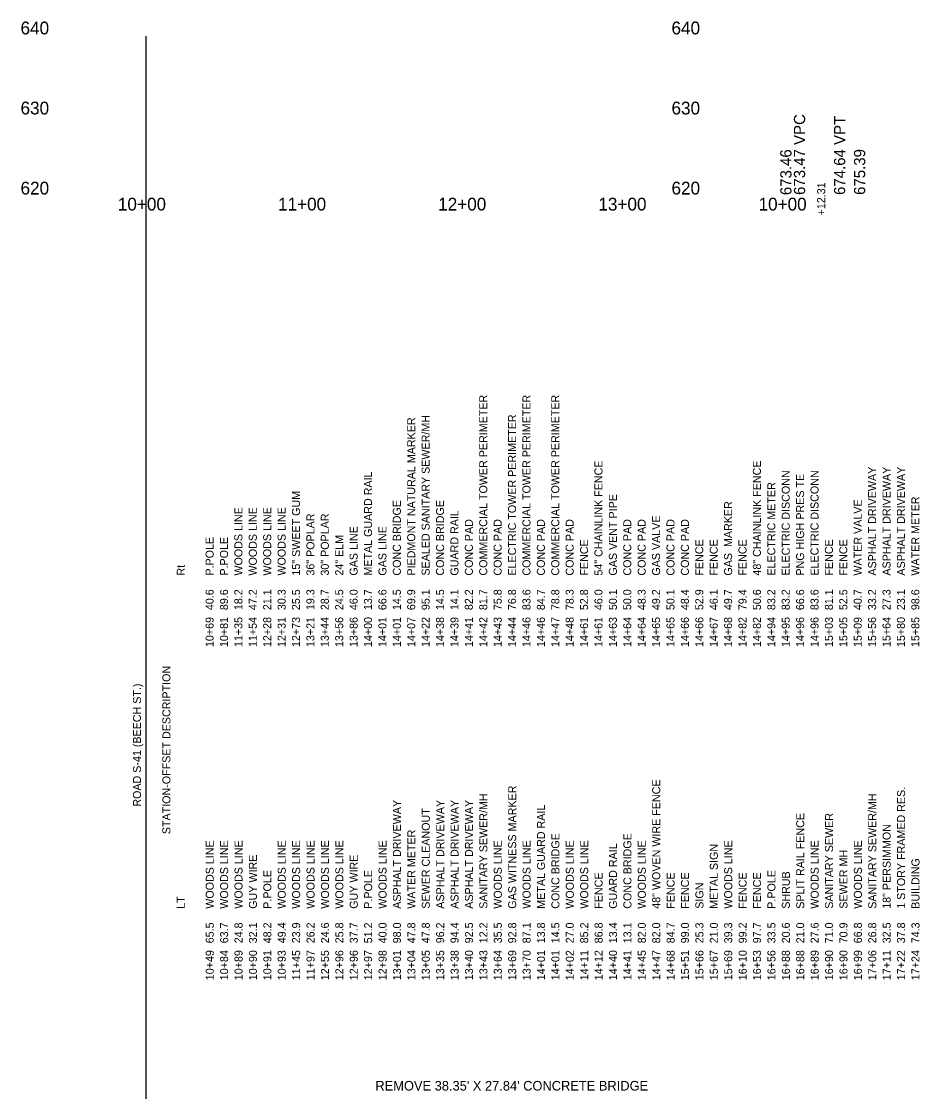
# Model space of a CAD drawing. Extents: x 16382402 to 16388022, y 46194326 to 46202918.
# Drawn here: x 16384274 to 16384834, y 46196212 to 46196880 of the extents above; entities that cross this region are included whole.
import ezdxf

# ---------------------------------------------------------------- set-up
doc = ezdxf.new("R2010")
doc.units = 0
for name, color, linetype in [('RD_DDB_ElevTX', 7, 'Continuous'), ('RD_DDB_Profile_Lbl', 7, 'Continuous'), ('RD_DDB_StaTX', 7, 'Continuous'), ('RD_DDB_StripGrade', 7, 'Continuous'), ('RD_EX_Bridge', 7, 'Continuous'), ('RD_GPK_Profile_Cell', 7, 'Continuous'), ('RD_TX_Bldg', 7, 'Continuous'), ('RD_TX_Misc1', 7, 'Continuous')]:
    doc.layers.add(name, color=color, linetype=linetype)

msp = doc.modelspace()

# ---------------------------------------------------------------- linework, layer by layer
at = {"layer": 'RD_GPK_Profile_Cell'}
msp.add_line((16384351.35, 46195620.8), (16384351.35, 46196870.8), dxfattribs=at)

# ---------------------------------------------------------------- texts
at = {"layer": 'RD_DDB_ElevTX'}
for s, p in [('640', (16384273.02, 46196871.8)), ('640', (16384679.41, 46196871.8)), ('630', (16384273.02, 46196821.8)), ('630', (16384679.41, 46196821.8)), ('620', (16384273.02, 46196771.8)), ('620', (16384679.41, 46196771.8))]:
    msp.add_text(s, height=8, dxfattribs=at).set_placement(p)
at = {"layer": 'RD_DDB_Profile_Lbl'}
msp.add_text('673.46', height=7, rotation=90, dxfattribs=at).set_placement((16384754.33, 46196771.42))
at = {"layer": 'RD_DDB_StaTX'}
msp.add_text('+12.31', height=5, rotation=90, dxfattribs=at).set_placement((16384775.36, 46196758.75))
for s, p in [('10+00', (16384333.76, 46196761.8)), ('11+00', (16384433.76, 46196761.8)), ('12+00', (16384533.76, 46196761.8)), ('13+00', (16384633.76, 46196761.8)), ('10+00', (16384733.76, 46196761.8))]:
    msp.add_text(s, height=8, dxfattribs=at).set_placement(p)
at = {"layer": 'RD_DDB_StripGrade'}
for s, p in [('673.47 VPC', (16384762.85, 46196771.53)), ('674.64 VPT', (16384787.85, 46196771.53)), ('675.39', (16384800.35, 46196771.55)), ('675.39', (16384800.35, 46196771.55))]:
    msp.add_text(s, height=7, rotation=90, dxfattribs=at).set_placement(p)
at = {"layer": 'RD_EX_Bridge'}
msp.add_text("REMOVE 38.35' X 27.84' CONCRETE BRIDGE", height=6, dxfattribs=at).set_placement((16384494.56, 46196212.2))
at = {"layer": 'RD_TX_Bldg'}
for s, p in [('COMMERCIAL TOWER PERIMETER', (16384564.39, 46196533.81)), ('COMMERCIAL TOWER PERIMETER', (16384591.37, 46196533.81)), ('COMMERCIAL TOWER PERIMETER', (16384609.35, 46196533.81)), ('SEALED SANITARY SEWER/MH', (16384528.42, 46196533.81)), ('ELECTRIC TOWER PERIMETER', (16384582.38, 46196533.81)), ('PIEDMONT NATURAL MARKER', (16384519.43, 46196533.81)), ('54" CHAINLINK FENCE', (16384636.33, 46196533.81)), ('48" CHAINLINK FENCE', (16384735.24, 46196533.81)), ('ASPHALT DRIVEWAY', (16384807.17, 46196533.81)), ('ASPHALT DRIVEWAY', (16384816.16, 46196533.81)), ('ASPHALT DRIVEWAY', (16384825.15, 46196533.81)), ('METAL GUARD RAIL', (16384492.46, 46196533.81)), ('ELECTRIC DISCONN', (16384753.22, 46196533.81)), ('PNG HIGH PRES TE', (16384762.21, 46196533.81)), ('ELECTRIC DISCONN', (16384771.2, 46196533.81)), ('ELECTRIC METER', (16384744.23, 46196533.81)), ('15" SWEET GUM', (16384447.5, 46196533.81)), ('CONC BRIDGE', (16384510.44, 46196533.81)), ('CONC BRIDGE', (16384537.42, 46196533.81)), ('GAS VENT PIPE', (16384645.32, 46196533.81)), ('GAS  MARKER', (16384717.25, 46196533.81)), ('WATER VALVE', (16384798.18, 46196533.81)), ('WATER METER', (16384834.14, 46196533.81)), ('WOODS LINE', (16384411.53, 46196533.81)), ('WOODS LINE', (16384420.52, 46196533.81)), ('WOODS LINE', (16384429.52, 46196533.81)), ('WOODS LINE', (16384438.51, 46196533.81)), ('GUARD RAIL', (16384546.41, 46196533.81)), ('36" POPLAR', (16384456.49, 46196533.81)), ('30" POPLAR', (16384465.48, 46196533.81)), ('CONC PAD', (16384555.4, 46196533.81)), ('CONC PAD', (16384573.38, 46196533.81)), ('CONC PAD', (16384600.36, 46196533.81)), ('CONC PAD', (16384618.34, 46196533.81)), ('CONC PAD', (16384654.31, 46196533.81)), ('CONC PAD', (16384663.3, 46196533.81)), ('GAS VALVE', (16384672.29, 46196533.81)), ('CONC PAD', (16384681.28, 46196533.81)), ('CONC PAD', (16384690.28, 46196533.81)), ('GAS LINE', (16384483.47, 46196533.81)), ('GAS LINE', (16384501.45, 46196533.81)), ('P.POLE', (16384393.55, 46196533.81)), ('P.POLE', (16384402.54, 46196533.81)), ('24" ELM', (16384474.47, 46196533.81)), ('FENCE', (16384627.33, 46196533.81)), ('FENCE', (16384699.27, 46196533.81)), ('FENCE', (16384708.26, 46196533.81)), ('FENCE', (16384726.24, 46196533.81)), ('FENCE', (16384780.19, 46196533.81)), ('FENCE', (16384789.19, 46196533.81)), ('Rt', (16384375.56, 46196533.81)), ('40.6', (16384393.55, 46196512.24)), ('89.6', (16384402.54, 46196512.24)), ('18.2', (16384411.53, 46196512.24)), ('47.2', (16384420.52, 46196512.24)), ('21.1', (16384429.52, 46196512.24)), ('30.3', (16384438.51, 46196512.24)), ('25.5', (16384447.5, 46196512.24)), ('19.3', (16384456.49, 46196512.24)), ('28.7', (16384465.48, 46196512.24)), ('24.5', (16384474.47, 46196512.24)), ('46.0', (16384483.47, 46196512.24)), ('13.7', (16384492.46, 46196512.24)), ('66.6', (16384501.45, 46196512.24)), ('14.5', (16384510.44, 46196512.24)), ('69.9', (16384519.43, 46196512.24)), ('95.1', (16384528.42, 46196512.24)), ('14.5', (16384537.42, 46196512.24)), ('14.1', (16384546.41, 46196512.24)), ('82.2', (16384555.4, 46196512.24)), ('81.7', (16384564.39, 46196512.24)), ('75.8', (16384573.38, 46196512.24)), ('76.8', (16384582.38, 46196512.24)), ('83.6', (16384591.37, 46196512.24)), ('84.7', (16384600.36, 46196512.24)), ('78.8', (16384609.35, 46196512.24)), ('78.3', (16384618.34, 46196512.24)), ('52.8', (16384627.33, 46196512.24)), ('46.0', (16384636.33, 46196512.24)), ('50.1', (16384645.32, 46196512.24)), ('50.0', (16384654.31, 46196512.24)), ('48.3', (16384663.3, 46196512.24)), ('49.2', (16384672.29, 46196512.24)), ('50.1', (16384681.28, 46196512.24)), ('48.4', (16384690.28, 46196512.24)), ('52.9', (16384699.27, 46196512.24)), ('46.1', (16384708.26, 46196512.24)), ('49.7', (16384717.25, 46196512.24)), ('79.4', (16384726.24, 46196512.24)), ('50.6', (16384735.24, 46196512.24)), ('83.2', (16384744.23, 46196512.24)), ('83.2', (16384753.22, 46196512.24)), ('66.6', (16384762.21, 46196512.24)), ('83.6', (16384771.2, 46196512.24)), ('81.1', (16384780.19, 46196512.24)), ('52.5', (16384789.19, 46196512.24)), ('40.7', (16384798.18, 46196512.24)), ('33.2', (16384807.17, 46196512.24)), ('27.3', (16384816.16, 46196512.24)), ('23.1', (16384825.15, 46196512.24)), ('98.6', (16384834.14, 46196512.24)), ('10+69', (16384393.55, 46196489.18)), ('10+81', (16384402.54, 46196489.18)), ('11+35', (16384411.53, 46196489.18)), ('11+54', (16384420.52, 46196489.18)), ('12+28', (16384429.52, 46196489.18)), ('12+31', (16384438.51, 46196489.18)), ('12+73', (16384447.5, 46196489.18)), ('13+21', (16384456.49, 46196489.18)), ('13+44', (16384465.48, 46196489.18)), ('13+56', (16384474.47, 46196489.18)), ('13+86', (16384483.47, 46196489.18)), ('14+00', (16384492.46, 46196489.18)), ('14+01', (16384501.45, 46196489.18)), ('14+01', (16384510.44, 46196489.18)), ('14+07', (16384519.43, 46196489.18)), ('14+22', (16384528.42, 46196489.18)), ('14+38', (16384537.42, 46196489.18)), ('14+39', (16384546.41, 46196489.18)), ('14+41', (16384555.4, 46196489.18)), ('14+42', (16384564.39, 46196489.18)), ('14+43', (16384573.38, 46196489.18)), ('14+44', (16384582.38, 46196489.18)), ('14+46', (16384591.37, 46196489.18)), ('14+46', (16384600.36, 46196489.18)), ('14+47', (16384609.35, 46196489.18)), ('14+48', (16384618.34, 46196489.18)), ('14+61', (16384627.33, 46196489.18)), ('14+61', (16384636.33, 46196489.18)), ('14+63', (16384645.32, 46196489.18)), ('14+64', (16384654.31, 46196489.18)), ('14+64', (16384663.3, 46196489.18)), ('14+65', (16384672.29, 46196489.18)), ('14+65', (16384681.28, 46196489.18)), ('14+66', (16384690.28, 46196489.18)), ('14+66', (16384699.27, 46196489.18)), ('14+67', (16384708.26, 46196489.18)), ('14+68', (16384717.25, 46196489.18)), ('14+82', (16384726.24, 46196489.18)), ('14+82', (16384735.24, 46196489.18)), ('14+94', (16384744.23, 46196489.18)), ('14+95', (16384753.22, 46196489.18)), ('14+96', (16384762.21, 46196489.18)), ('14+96', (16384771.2, 46196489.18)), ('15+03', (16384780.19, 46196489.18)), ('15+05', (16384789.19, 46196489.18)), ('15+09', (16384798.18, 46196489.18)), ('15+56', (16384807.17, 46196489.18)), ('15+64', (16384816.16, 46196489.18)), ('15+80', (16384825.15, 46196489.18)), ('15+85', (16384834.14, 46196489.18)), ('STATION-OFFSET DESCRIPTION', (16384366.58, 46196372.32)), ('ROAD S-41 (BEECH ST.)', (16384348.22, 46196389.5)), ('48" WOVEN WIRE FENCE', (16384672.38, 46196325.74)), ('GAS WITNESS MARKER', (16384582.46, 46196325.74)), ('ASPHALT DRIVEWAY', (16384510.52, 46196325.74)), ('ASPHALT DRIVEWAY', (16384537.5, 46196325.74)), ('ASPHALT DRIVEWAY', (16384546.49, 46196325.74)), ('ASPHALT DRIVEWAY', (16384555.48, 46196325.74)), ('SANITARY SEWER/MH', (16384564.47, 46196325.74)), ('SEWER CLEANOUT', (16384528.51, 46196325.74)), ('METAL GUARD RAIL', (16384600.44, 46196325.74)), ('WATER METER', (16384519.52, 46196325.74)), ('CONC BRIDGE', (16384609.43, 46196325.74)), ('CONC BRIDGE', (16384654.39, 46196325.74)), ('WOODS LINE', (16384465.57, 46196325.74)), ('WOODS LINE', (16384474.56, 46196325.74)), ('WOODS LINE', (16384501.53, 46196325.74)), ('WOODS LINE', (16384573.47, 46196325.74)), ('WOODS LINE', (16384591.45, 46196325.74)), ('WOODS LINE', (16384618.42, 46196325.74)), ('WOODS LINE', (16384627.42, 46196325.74)), ('GUARD RAIL', (16384645.4, 46196325.74)), ('WOODS LINE', (16384663.38, 46196325.74)), ('GUY WIRE', (16384483.55, 46196325.74)), ('P.POLE', (16384492.54, 46196325.74)), ('FENCE', (16384636.41, 46196325.74)), ('FENCE', (16384681.37, 46196325.74)), ('LT', (16384375.57, 46196325.74)), ('24.6', (16384465.57, 46196304.16)), ('25.8', (16384474.56, 46196304.16)), ('37.7', (16384483.55, 46196304.16)), ('51.2', (16384492.54, 46196304.16)), ('40.0', (16384501.53, 46196304.16)), ('98.0', (16384510.52, 46196304.16)), ('47.8', (16384519.52, 46196304.16)), ('47.8', (16384528.51, 46196304.16)), ('96.2', (16384537.5, 46196304.16)), ('94.4', (16384546.49, 46196304.16)), ('92.5', (16384555.48, 46196304.16)), ('12.2', (16384564.47, 46196304.16)), ('35.5', (16384573.47, 46196304.16)), ('92.8', (16384582.46, 46196304.16)), ('87.1', (16384591.45, 46196304.16)), ('13.8', (16384600.44, 46196304.16)), ('14.5', (16384609.43, 46196304.16)), ('27.0', (16384618.42, 46196304.16)), ('85.2', (16384627.42, 46196304.16)), ('86.8', (16384636.41, 46196304.16)), ('13.4', (16384645.4, 46196304.16)), ('13.1', (16384654.39, 46196304.16)), ('82.0', (16384663.38, 46196304.16)), ('82.0', (16384672.38, 46196304.16)), ('84.7', (16384681.37, 46196304.16)), ('12+55', (16384465.57, 46196281.11)), ('12+96', (16384474.56, 46196281.11)), ('12+96', (16384483.55, 46196281.11)), ('12+97', (16384492.54, 46196281.11)), ('12+98', (16384501.53, 46196281.11)), ('13+01', (16384510.52, 46196281.11)), ('13+04', (16384519.52, 46196281.11)), ('13+05', (16384528.51, 46196281.11)), ('13+35', (16384537.5, 46196281.11)), ('13+38', (16384546.49, 46196281.11)), ('13+40', (16384555.48, 46196281.11)), ('13+43', (16384564.47, 46196281.11)), ('13+64', (16384573.47, 46196281.11)), ('13+69', (16384582.46, 46196281.11)), ('13+70', (16384591.45, 46196281.11)), ('14+01', (16384600.44, 46196281.11)), ('14+01', (16384609.43, 46196281.11)), ('14+02', (16384618.42, 46196281.11)), ('14+11', (16384627.42, 46196281.11)), ('14+12', (16384636.41, 46196281.11)), ('14+40', (16384645.4, 46196281.11)), ('14+41', (16384654.39, 46196281.11)), ('14+45', (16384663.38, 46196281.11)), ('14+47', (16384672.38, 46196281.11)), ('14+68', (16384681.37, 46196281.11))]:
    msp.add_text(s, height=5, rotation=90, dxfattribs=at).set_placement(p)
at = {"layer": 'RD_TX_Misc1'}
for s, p in [('1 STORY FRAMED RES.', (16384825.24, 46196325.74)), ('SANITARY SEWER/MH', (16384807.25, 46196325.74)), ('SPLIT RAIL FENCE', (16384762.29, 46196325.74)), ('SANITARY SEWER', (16384780.28, 46196325.74)), ('18" PERSIMMON', (16384816.24, 46196325.74)), ('WOODS LINE', (16384393.63, 46196325.74)), ('WOODS LINE', (16384402.62, 46196325.74)), ('WOODS LINE', (16384411.61, 46196325.74)), ('WOODS LINE', (16384438.59, 46196325.74)), ('WOODS LINE', (16384447.58, 46196325.74)), ('WOODS LINE', (16384456.57, 46196325.74)), ('METAL SIGN', (16384708.34, 46196325.74)), ('WOODS LINE', (16384717.33, 46196325.74)), ('WOODS LINE', (16384771.28, 46196325.74)), ('WOODS LINE', (16384798.26, 46196325.74)), ('GUY WIRE', (16384420.61, 46196325.74)), ('SEWER MH', (16384789.27, 46196325.74)), ('BUILDING', (16384834.23, 46196325.74)), ('P.POLE', (16384429.6, 46196325.74)), ('FENCE', (16384690.36, 46196325.74)), ('FENCE', (16384726.33, 46196325.74)), ('FENCE', (16384735.32, 46196325.74)), ('P.POLE', (16384744.31, 46196325.74)), ('SHRUB', (16384753.3, 46196325.74)), ('SIGN', (16384699.35, 46196325.74)), ('65.5', (16384393.63, 46196304.16)), ('63.7', (16384402.62, 46196304.16)), ('24.8', (16384411.61, 46196304.16)), ('32.1', (16384420.61, 46196304.16)), ('48.2', (16384429.6, 46196304.16)), ('49.4', (16384438.59, 46196304.16)), ('23.9', (16384447.58, 46196304.16)), ('26.2', (16384456.57, 46196304.16)), ('99.0', (16384690.36, 46196304.16)), ('25.3', (16384699.35, 46196304.16)), ('21.0', (16384708.34, 46196304.16)), ('39.3', (16384717.33, 46196304.16)), ('99.2', (16384726.33, 46196304.16)), ('97.7', (16384735.32, 46196304.16)), ('33.5', (16384744.31, 46196304.16)), ('20.6', (16384753.3, 46196304.16)), ('21.0', (16384762.29, 46196304.16)), ('27.6', (16384771.28, 46196304.16)), ('71.0', (16384780.28, 46196304.16)), ('70.9', (16384789.27, 46196304.16)), ('66.8', (16384798.26, 46196304.16)), ('26.8', (16384807.25, 46196304.16)), ('32.5', (16384816.24, 46196304.16)), ('37.8', (16384825.24, 46196304.16)), ('74.3', (16384834.23, 46196304.16)), ('10+49', (16384393.63, 46196281.11)), ('10+84', (16384402.62, 46196281.11)), ('10+89', (16384411.61, 46196281.11)), ('10+90', (16384420.61, 46196281.11)), ('10+91', (16384429.6, 46196281.11)), ('10+93', (16384438.59, 46196281.11)), ('11+45', (16384447.58, 46196281.11)), ('11+97', (16384456.57, 46196281.11)), ('15+51', (16384690.36, 46196281.11)), ('15+66', (16384699.35, 46196281.11)), ('15+67', (16384708.34, 46196281.11)), ('15+69', (16384717.33, 46196281.11)), ('16+10', (16384726.33, 46196281.11)), ('16+53', (16384735.32, 46196281.11)), ('16+56', (16384744.31, 46196281.11)), ('16+88', (16384753.3, 46196281.11)), ('16+88', (16384762.29, 46196281.11)), ('16+89', (16384771.28, 46196281.11)), ('16+90', (16384780.28, 46196281.11)), ('16+90', (16384789.27, 46196281.11)), ('16+99', (16384798.26, 46196281.11)), ('17+06', (16384807.25, 46196281.11)), ('17+11', (16384816.24, 46196281.11)), ('17+22', (16384825.24, 46196281.11)), ('17+24', (16384834.23, 46196281.11))]:
    msp.add_text(s, height=5, rotation=90, dxfattribs=at).set_placement(p)

doc.saveas('drawing.dxf')
